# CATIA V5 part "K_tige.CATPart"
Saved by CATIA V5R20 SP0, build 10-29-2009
Part number: tige
Publications: "Plan.3", "Corps principal", "Point.4", "Plan.12"
Bounding box of the stored display mesh (mm): x -72 to 72, y -50 to 116.999, z -10 to 754
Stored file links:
  G:\Khaled_CFAO_2011\ST2M\ST2M_GR2\echouteau\Khaled\CAD_ThinkMotion\K_tige.CATPart
  F:\2A\Proj Think Motion\trainv3\Version3\sql_general.CATProduct
  G:\Khaled_CFAO_2011\ST2M\ST2M_GR2\echouteau\Khaled\CAD_ThinkMotion\K_general.CATPart
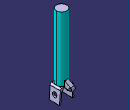
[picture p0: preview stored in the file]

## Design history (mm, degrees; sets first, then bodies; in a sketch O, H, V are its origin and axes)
Parameters
  Longueur_tige = 700 mm
External parameters (linked from other documents)
  External.Ecart_tige_corps = 150 mm
Set1
  Plane1 "plan_ref": linked copy from another document
  Plane2: linked copy from another document
Body1 (main body)
  Plane3: type Offset, RefPlane Plane1, Offset 700 {= Longueur_tige}
  Point1: type OnPlane, Support Plane1, H 0, V 0, Direction (1, 0, 0)
  Point2: type OnPlane, Support Plane3, H 0, V 0, Direction (1, 0, 0)
  Line1 "tige": type PtPt, FirstPoint Point1, SecondPoint Point2
  Plane4: type Offset, RefPlane Plane1, Offset 150 {= External.Ecart_tige_corps}
  Plane5: type Offset, RefPlane Plane4, Offset -80
  Point3: type OnPlane, Support Plane5, H 0, V 0, Direction (1, 0, 0)
  Point4: type OnPlane, Support Plane5, H 0, V 100, Direction (1, 0, 0)
  Line2: type PtPt, FirstPoint Point4, SecondPoint Point3
  Plane6: type OffsetPt, RefPlane Plane2, RefPoint Point3
  Line3: type PtDir, RefPoint Point1, Direction yz-plane, Start 0, End 166
  Plane7: type OffsetPt, RefPlane yz-plane, RefPoint vertex of Line3
  Line4: type PtDir, RefPoint Point4, Direction yz-plane, Start 0, End -145
  Plane8: type OffsetPt, RefPlane yz-plane, RefPoint vertex of Line4
  Sketch1 on Plane5, origin (0, 0, 124), H (1, 0, 0), V (0, 1, 0)
    circle A1 centre (0, 0) radius 50
    point P1 (0, 0)
    reference projected point E1 (0, 0) from Point1
    coincidence: P1 E1
  Pad1: profile Sketch1, direction (0, 0, 1), up to Plane3
  Plane9: stored without definition
  Sketch2 on zx-plane, origin (0, 0, 0), H (-1, 0, 0), V (0, 0, 1)
    point P1 (0, 124)
    reference projected point E1 (0, 124) from Point3
    point P2 (0, 124)
    line L1 (0, 124) -> (47.2736, 124)
    line L2 (63.2305, 109.1742) -> (72, -10)
    point P3 (72, -10)
    arc A1 centre (47.2736, 108) radius 16 from (47.2736, 124) to (63.2305, 109.1742) cw
    point P4 (47.2736, 124)
    point P5 (63.2305, 109.1742)
    line L3 (0, 117.2535) -> (5.4731, 117.4252)
    point P6 (0, 117.2535)
    line L4 (49.6241, 78.5552) -> (58.1251, -10)
    point P7 (58.1251, -10)
    line L5 (58.1251, -10) -> (72, -10)
    arc A2 centre (6.8209, 74.4463) radius 43 from (5.4731, 117.4252) to (49.6241, 78.5552) cw
    point P8 (5.4731, 117.4252)
    point P9 (49.6241, 78.5552)
    point P10 (-47.2736, 124)
    point P11 (0, 124)
    line L6 (0, 124) -> (-47.2736, 124)
    point P12 (-63.2305, 109.1742)
    arc A3 centre (-47.2736, 108) radius 16 from (-47.2736, 124) to (-63.2305, 109.1742) ccw
    point P13 (-72, -10)
    line L7 (-63.2305, 109.1742) -> (-72, -10)
    point P14 (-58.1251, -10)
    line L8 (-58.1251, -10) -> (-72, -10)
    point P15 (-49.6241, 78.5552)
    line L9 (-49.6241, 78.5552) -> (-58.1251, -10)
    point P16 (-5.4731, 117.4252)
    arc A4 centre (-6.8209, 74.4463) radius 43 from (-5.4731, 117.4252) to (-49.6241, 78.5552) ccw
    point P17 (0, 117.2535)
    line L10 (0, 117.2535) -> (-5.4731, 117.4252)
    radius A1 = 16
    radius A2 = 43
    coincidence: E1 P1, P1 P2, P6 V
    symmetry: P1 P2 V, P4 P10 V, P1 P11 V, L1 L6 V, P5 P12 V, A1 A3 V, P3 P13 V, L2 L7 V, P7 P14 V, L5 L8 V, P9 P15 V, L4 L9 V, P8 P16 V, A2 A4 V, P6 P17 V, L3 L10 V
    horizontal: L1 H, L5 H
    tangency: A1 L1, A1 L2, A2 L3, A2 L4
  Sketch3 on start face of Pad1, origin (0, 0, 124), H (1, 0, 0), V (0, -1, 0)
    line L1 (0, 50) -> (-75, 50)
    point P1 (0, 50)
    point P2 (-75, 50)
    line L2 (-75, 50) -> (-75, 0)
    point P3 (-75, 0)
    point P4 (-75, 0)
    point P5 (-75, -50)
    line L3 (-75, -50) -> (-75, 0)
    point P6 (0, -50)
    line L4 (0, -50) -> (-75, -50)
    point P7 (75, 50)
    point P8 (0, 50)
    line L5 (0, 50) -> (75, 50)
    point P9 (75, 0)
    line L6 (75, 50) -> (75, 0)
    point P10 (75, 0)
    point P11 (75, -50)
    line L7 (75, -50) -> (75, 0)
    point P12 (0, -50)
    line L8 (0, -50) -> (75, -50)
    distance P7 P2 = 150
    distance P7 P11 = 100
    coincidence: P1 V, P3 H, P1 P8, P3 P4, P6 P12, P9 P10
    horizontal: L1 H
    vertical: L2 V
    symmetry: P3 P4 H, P2 P5 H, L2 L3 H, P1 P6 H, L1 L4 H, P2 P7 V, P1 P8 V, L1 L5 V, P3 P9 V, L2 L6 V, P4 P10 V, P5 P11 V, L3 L7 V, P6 P12 V, L4 L8 V
  SolidCombine1: FirstComponentProfile Sketch2, FirstComponentDirection Sketch2, SecondComponentProfile Sketch3, SecondComponentDirection Sketch3
  Line5: stored without definition
  Line6: stored without definition
  Point5 to Point7: stored without definition
  Sketch4 on yz-plane, origin (0, 0, 0), H (0, 1, 0), V (0, 0, 1)
    line L1 (106.3583, 139.7662) -> (35.9863, 176.6426)
    point P1 (106.3583, 139.7662)
    point P2 (35.9863, 176.6426)
    line L2 (35.9863, 176.6426) -> (35.9863, 116.6426)
    point P3 (35.9863, 116.6426)
    reference projected line E1 (50, 123.766) -> (50, 74.6396) from edge [face of SolidCombine1 from Sketch3.L7 | face of SolidCombine1 from Sketch3.L8]
    line L3 (99.398, 107.0107) -> (35.9863, 116.6426)
    reference projected point E2 (100, 124) from Point6
    arc A1 centre (100, 124) radius 17 from (99.398, 107.0107) to (106.3583, 139.7662) ccw
    point P4 (100, 124)
    reference projected point E3 (100, 124) from Point7
    distance P2 P3 = 60
    distance E2 P1 = 17
    vertical: L2 V
    parallelism: L2 E1
    coincidence: P4 E3
  Point8: stored without definition
  Sketch5 on zx-plane, origin (0, 0, 0), H (-1, 0, 0), V (0, 0, 1)
    point P1 (0, 107)
    line L1 (0, 107) -> (18, 107)
    line L2 (18, 107) -> (18, 174)
    line L3 (18, 174) -> (0, 174)
    point P2 (18, 107)
    point P3 (18, 174)
    point P4 (0, 174)
    point P5 (0, 174)
    point P6 (-18, 174)
    line L4 (-18, 174) -> (0, 174)
    point P7 (-18, 107)
    line L5 (-18, 107) -> (-18, 174)
    point P8 (0, 107)
    line L6 (0, 107) -> (-18, 107)
    reference projected point E1 (0, 124) from Point8
    distance E1 P4 = 50
    distance P3 P2 = 67
    length L3 = 18
    coincidence: P1 V, P1 P8, P4 P5
    horizontal: L1 H, L3 H
    vertical: L2 V
    symmetry: P4 P5 V, P3 P6 V, L3 L4 V, P2 P7 V, L2 L5 V, P1 P8 V, L1 L6 V
  SolidCombine2: FirstComponentProfile Sketch4, FirstComponentDirection Sketch4, SecondComponentProfile Sketch5, SecondComponentDirection Sketch5
  Plane10: stored without definition
  Sketch6 on Plane7, origin (166, -1.0857, 45.6448), H (0, 1, 0), V (0, 0, 1)
    point P1 (1.0857, 8.3552)
    reference projected point E1 (1.0857, 8.3552) from Point1
    coincidence: P1 E1
  Hole1: placed by Sketch6, at (166, 0, 54) direction (-1, 0, 0), diameter 45, up to Plane10
  Sketch7 on face of SolidCombine2 from Sketch5.L5, origin (18, 116.5615, 124.6209), H (0, 1, 0), V (0, 0, 1)
    point P1 (-16.5615, -0.6209)
    reference projected arc E1 centre (-16.5615, -0.6209) radius 17 from (-17.1636, -17.6102) to (-19.2211, 16.1698) ccw from Sketch4.A1
    concentricity: P1 E1
  Hole2: placed by Sketch7, at (18, 100, 124) direction (-1, 0, 0), diameter 20, up to face of SolidCombine2 from Sketch5.L2
  Plane11: type OffsetPt, RefPlane Plane7, RefPoint Point1
  Point9: type Center, Curve edge [face of SolidCombine1 from Sketch2.L2 | face of Hole1]
  Point10: type Center, Curve edge [face of Hole1 | face of SolidCombine1 from Sketch2.L7]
